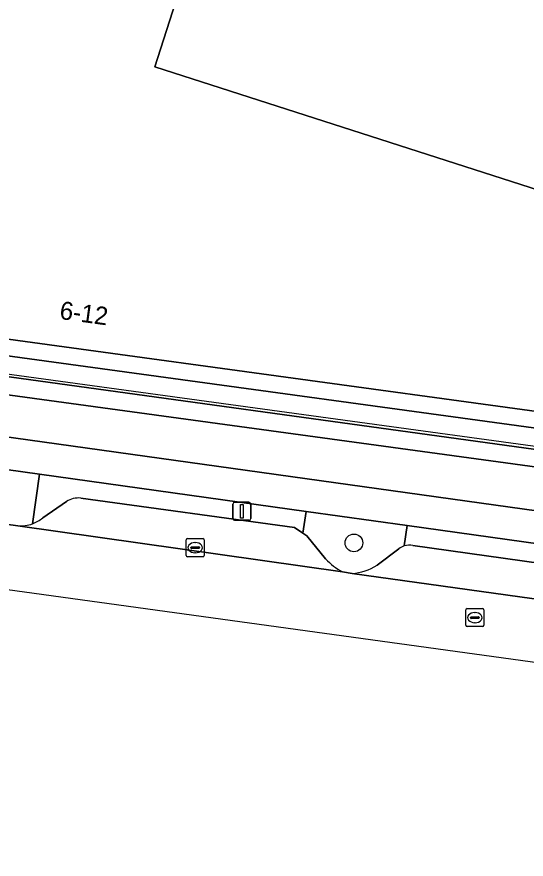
# Model space of a CAD drawing. Extents: x 160675 to 161153, y 383241 to 383714.
# Drawn here: x 160930.14 to 160958.41, y 383243.61 to 383290.36 of the extents above; entities that cross this region are included whole.
import ezdxf

# ---------------------------------------------------------------- set-up
doc = ezdxf.new("R2010")
doc.units = 0
for name, color, linetype in [('IMGEO_Berm_open', 7, 'Continuous'), ('IMGEO_Boom', 7, 'Continuous'), ('IMGEO_Erf', 7, 'Continuous'), ('IMGEO_Fietspad_gesloten', 7, 'Continuous'), ('IMGEO_Groenvoorziening', 7, 'Continuous'), ('IMGEO_Kolk', 7, 'Continuous'), ('IMGEO_Lichtmast', 7, 'Continuous'), ('IMGEO_Lijnafwatering', 7, 'Continuous'), ('IMGEO_Pand', 7, 'Continuous'), ('IMGEO_Pand_nummerreeks', 7, 'Continuous'), ('IMGEO_Parkeervlak_open', 7, 'Continuous'), ('IMGEO_Rijbaan_lokaal_gesloten', 7, 'Continuous'), ('IMGEO_Rioolput', 7, 'Continuous'), ('IMGEO_Voetpad_open', 7, 'Continuous')]:
    doc.layers.add(name, color=color, linetype=linetype)

msp = doc.modelspace()

# ---------------------------------------------------------------- linework, layer by layer
at = {"layer": 'IMGEO_Berm_open'}
for points in [[(160946.189, 383262.908), (160931.387, 383264.979), (160931.002, 383262.219)], [(160933.685, 383263.646), (160945.542, 383262.006), (160946.008, 383261.707), (160946.189, 383262.908)], [(160931.577, 383262.554), (160932.889, 383263.454)], [(160951.803, 383262.123), (160951.638, 383260.989)], [(160970.944, 383258.256), (160971.094, 383259.424), (160951.803, 383262.123)], [(160952.119, 383261.02), (160970.455, 383258.441)]]:
    msp.add_lwpolyline(points, dxfattribs=at)
for centre, radius, start, end in [((160933.559, 383262.422), 1.231, 84.1317, 122.9904), ((160930.363, 383263.977), 1.87, 289.9775, 310.4734), ((160951.941, 383260.039), 0.997, 79.704, 107.6711)]:
    msp.add_arc(centre, radius, start, end, dxfattribs=at)
at = {"layer": 'IMGEO_Boom'}
msp.add_circle((160948.846, 383261.16), 0.489, dxfattribs=at)
at = {"layer": 'IMGEO_Erf'}
msp.add_lwpolyline([(160943.614, 383302.795), (160942.777, 383303.077), (160942.578, 383302.465), (160941.73, 383302.736), (160940.32, 383298.343), (160941.191, 383298.065), (160940.991, 383297.445), (160940.143, 383297.716), (160938.625, 383292.988), (160939.448, 383292.73), (160937.804, 383287.581), (160963.866, 383279.201), (160968.854, 383294.685)], close=True, dxfattribs=at)
at = {"layer": 'IMGEO_Fietspad_gesloten'}
for points in [[(161055.654, 383249.406), (161021.974, 383254.146), (161015.584, 383255.032), (160917.876, 383268.672), (160905.957, 383270.323), (160821.26, 383282.051), (160802.2, 383284.6)], [(160916.557, 383267.054), (160927.544, 383265.517), (160931.387, 383264.979), (160946.189, 383262.908), (160951.803, 383262.123), (160971.094, 383259.424), (160976.57, 383258.658), (160989.408, 383256.862), (160994.582, 383256.138), (161009.264, 383254.084), (161014.233, 383253.389), (161021.034, 383252.455), (161029.904, 383251.214), (161035.545, 383250.425), (161050.235, 383248.369), (161054.045, 383247.836), (161056.61, 383247.477)]]:
    msp.add_lwpolyline(points, dxfattribs=at)
at = {"layer": 'IMGEO_Groenvoorziening'}
for points in [[(160931.387, 383264.979), (160927.544, 383265.517), (160927.098, 383262.525), (160930.19, 383262.116)], [(160931.002, 383262.219), (160931.387, 383264.979)], [(160951.803, 383262.123), (160946.189, 383262.908), (160946.008, 383261.707), (160946.238, 383261.56), (160947.276, 383260.282)], [(160951.638, 383260.989), (160951.803, 383262.123)], [(160950.129, 383259.921), (160951.342, 383260.833)], [(160948.208, 383259.553), (160948.745, 383259.454)]]:
    msp.add_lwpolyline(points, dxfattribs=at)
for centre, radius, start, end in [((160930.366, 383263.979), 1.871, 264.5955, 289.8629), ((160951.928, 383260.079), 0.955, 107.7036, 127.8773), ((160949.729, 383262.458), 3.279, 221.5745, 242.3612), ((160948.423, 383262.692), 3.254, 275.6766, 301.615)]:
    msp.add_arc(centre, radius, start, end, dxfattribs=at)
at = {"layer": 'IMGEO_Kolk'}
for p, q in [((160939.535, 383260.469), (160939.535, 383261.321)), ((160939.61, 383261.395), (160940.462, 383261.395)), ((160940.536, 383261.321), (160940.536, 383260.469)), ((160939.794, 383260.889), (160939.794, 383260.901)), ((160940.232, 383260.852), (160939.834, 383260.852)), ((160939.837, 383260.938), (160940.235, 383260.938)), ((160940.023, 383261.175), (160940.048, 383261.175)), ((160940.278, 383260.901), (160940.278, 383260.889)), ((160940.462, 383260.395), (160939.61, 383260.395)), ((160940.046, 383260.615), (160940.021, 383260.615))]:
    msp.add_line(p, q, dxfattribs=at)
for points in [[(160939.535, 383260.469), (160939.535, 383261.321)], [(160939.61, 383261.395), (160940.462, 383261.395)], [(160940.536, 383261.321), (160940.536, 383260.469)], [(160940.462, 383260.395), (160939.61, 383260.395)]]:
    msp.add_lwpolyline(points, dxfattribs=at)
for centre, radius, start, end in [((160939.612, 383261.319), 0.0765, 91.552, 178.448), ((160939.612, 383261.319), 0.0765, 91.552, 178.448), ((160940.46, 383261.319), 0.0765, 1.552, 88.448), ((160940.46, 383261.319), 0.0765, 1.552, 88.448), ((160939.834, 383260.898), 0.0403, 85.8775, 175.7526), ((160939.831, 383260.888), 0.0366, 178.938, 274.7102), ((160940.235, 383260.895), 0.043, 264.8664, 352.4533), ((160940.239, 383260.9), 0.0386, 1.7309, 96.639), ((160939.612, 383260.471), 0.0765, 181.552, 268.448), ((160939.612, 383260.471), 0.0765, 181.552, 268.448), ((160940.46, 383260.471), 0.0765, 271.552, 358.448), ((160940.46, 383260.471), 0.0765, 271.552, 358.448)]:
    msp.add_arc(centre, radius, start, end, dxfattribs=at)
for centre, major_axis, ratio, start_param, end_param in [((160940.022, 383260.895), (-0.387, 0.002), 0.722429, 4.712389, 7.853982), ((160940.047, 383260.895), (-0.39, 0.002), 0.717154, 1.570796, 4.712389)]:
    msp.add_ellipse(centre, major_axis=major_axis, ratio=ratio, start_param=start_param, end_param=end_param, dxfattribs=at)
at = {"layer": 'IMGEO_Lichtmast'}
for p, q in [((160942.126, 383262.515), (160942.126, 383263.315)), ((160942.126, 383263.315), (160942.126, 383262.515)), ((160942.226, 383263.415), (160943.016, 383263.415)), ((160943.016, 383263.415), (160942.226, 383263.415)), ((160943.116, 383263.315), (160943.116, 383262.515)), ((160943.116, 383262.515), (160943.116, 383263.315)), ((160943.016, 383262.415), (160942.226, 383262.415)), ((160942.226, 383262.415), (160943.016, 383262.415))]:
    msp.add_line(p, q, dxfattribs=at)
msp.add_lwpolyline([(160942.546, 383263.29), (160942.696, 383263.29), (160942.696, 383262.54), (160942.546, 383262.54), (160942.546, 383263.29)], dxfattribs=at)
for centre, start, end in [((160942.226, 383263.315), 90, 180), ((160942.226, 383263.315), 90, 180), ((160943.016, 383263.315), 0, 90), ((160943.016, 383263.315), 360, 90), ((160942.226, 383262.515), 180, 270), ((160942.226, 383262.515), 180, 270), ((160943.016, 383262.515), 270, 0), ((160943.016, 383262.515), 270, 0)]:
    msp.add_arc(centre, 0.1, start, end, dxfattribs=at)
at = {"layer": 'IMGEO_Lijnafwatering'}
for points in [[(160931.212, 383270.307), (160913.243, 383272.77)], [(160949.181, 383267.844), (160931.212, 383270.307)], [(160967.149, 383265.381), (160949.181, 383267.844)]]:
    msp.add_lwpolyline(points, dxfattribs=at)
at = {"layer": 'IMGEO_Pand'}
msp.add_lwpolyline([(160920.037, 383273.784), (160958.187, 383268.56), (160960.344, 383268.267), (160963.866, 383279.201), (160937.804, 383287.581), (160939.448, 383292.73), (160938.625, 383292.988), (160940.143, 383297.716), (160940.991, 383297.445), (160941.191, 383298.065), (160940.32, 383298.343), (160941.73, 383302.736), (160942.578, 383302.465), (160942.777, 383303.077), (160933.386, 383306.103), (160933.536, 383306.474), (160933.134, 383306.606), (160932.393, 383304.302), (160927.197, 383305.975)], dxfattribs=at)
at = {"layer": 'IMGEO_Parkeervlak_open'}
for points in [[(160945.542, 383262.006), (160933.685, 383263.646)], [(160932.889, 383263.454), (160931.577, 383262.554)], [(160930.19, 383262.116), (160948.208, 383259.553)], [(160947.276, 383260.282), (160946.238, 383261.56), (160946.008, 383261.707), (160945.542, 383262.006)], [(160951.342, 383260.833), (160950.129, 383259.921)], [(160970.455, 383258.441), (160952.119, 383261.02)], [(160948.745, 383259.454), (160973.076, 383256.077)]]:
    msp.add_lwpolyline(points, dxfattribs=at)
for centre, radius, start, end in [((160933.559, 383262.422), 1.231, 84.1317, 122.9904), ((160930.366, 383263.979), 1.871, 264.5955, 289.8629), ((160930.363, 383263.977), 1.87, 289.9775, 310.4734), ((160951.928, 383260.079), 0.955, 107.7036, 127.8773), ((160951.941, 383260.039), 0.997, 79.704, 107.6711), ((160949.729, 383262.458), 3.279, 221.5745, 242.3612), ((160948.423, 383262.692), 3.254, 275.6766, 301.615)]:
    msp.add_arc(centre, radius, start, end, dxfattribs=at)
at = {"layer": 'IMGEO_Rijbaan_lokaal_gesloten'}
msp.add_lwpolyline([(160991.33, 383253.522), (160973.717, 383255.972), (160973.076, 383256.077), (160948.745, 383259.454), (160948.208, 383259.553), (160930.19, 383262.116), (160927.098, 383262.525), (160926.821, 383262.562), (160926.374, 383259.023), (161038.265, 383243.607)], dxfattribs=at)
at = {"layer": 'IMGEO_Rioolput'}
for p, q in [((160955.133, 383257.511), (160955.985, 383257.511)), ((160955.058, 383256.585), (160955.058, 383257.437)), ((160955.317, 383257.005), (160955.317, 383257.017)), ((160955.36, 383257.054), (160955.758, 383257.054)), ((160955.546, 383257.291), (160955.571, 383257.291)), ((160955.801, 383257.017), (160955.801, 383257.005)), ((160956.059, 383257.437), (160956.059, 383256.585)), ((160955.755, 383256.968), (160955.357, 383256.968)), ((160955.569, 383256.731), (160955.544, 383256.731)), ((160955.985, 383256.511), (160955.133, 383256.511))]:
    msp.add_line(p, q, dxfattribs=at)
for points in [[(160955.133, 383257.511), (160955.985, 383257.511)], [(160955.058, 383256.585), (160955.058, 383257.437)], [(160956.059, 383257.437), (160956.059, 383256.585)], [(160955.985, 383256.511), (160955.133, 383256.511)]]:
    msp.add_lwpolyline(points, dxfattribs=at)
for centre, radius, start, end in [((160955.135, 383257.435), 0.0765, 91.552, 178.448), ((160955.135, 383257.435), 0.0765, 91.552, 178.448), ((160955.983, 383257.435), 0.0765, 1.552, 88.448), ((160955.983, 383257.435), 0.0765, 1.552, 88.448), ((160955.357, 383257.014), 0.0403, 85.8775, 175.7526), ((160955.354, 383257.004), 0.0366, 178.938, 274.7102), ((160955.758, 383257.011), 0.043, 264.8664, 352.4533), ((160955.762, 383257.016), 0.0386, 1.7309, 96.639), ((160955.135, 383256.587), 0.0765, 181.552, 268.448), ((160955.135, 383256.587), 0.0765, 181.552, 268.448), ((160955.983, 383256.587), 0.0765, 271.552, 358.448), ((160955.983, 383256.587), 0.0765, 271.552, 358.448)]:
    msp.add_arc(centre, radius, start, end, dxfattribs=at)
for centre, major_axis, ratio, start_param, end_param in [((160955.545, 383257.011), (-0.387, 0.002), 0.722429, 4.712389, 7.853982), ((160955.57, 383257.011), (-0.39, 0.002), 0.717154, 1.570796, 4.712389)]:
    msp.add_ellipse(centre, major_axis=major_axis, ratio=ratio, start_param=start_param, end_param=end_param, dxfattribs=at)
at = {"layer": 'IMGEO_Voetpad_open'}
for points in [[(160794.456, 383285.635), (160802.2, 383284.6), (160821.26, 383282.051), (160905.957, 383270.323), (160917.876, 383268.672), (161015.584, 383255.032)], [(160906.361, 383274.718), (160906.652, 383275.617), (160907.414, 383278.054), (160906.582, 383278.383), (160904.953, 383273.337), (160904.857, 383273.04), (160905.752, 383272.875), (160905.772, 383272.934), (160905.926, 383273.383), (160906.572, 383273.293), (160906.425, 383272.844), (160912.494, 383272.008), (160912.693, 383272.666), (160919.42, 383271.745), (160919.491, 383271.792), (160966.461, 383265.316), (160973.144, 383264.419), (160988.15, 383262.381)], [(160987.9, 383263.299), (160987.726, 383263.594), (160906.361, 383274.718)], [(160988.114, 383261.392), (160972.847, 383263.465), (160972.925, 383263.763), (160966.242, 383264.66), (160966.18, 383264.374), (160960.071, 383265.21), (160959.949, 383264.845), (160959.305, 383264.94), (160959.423, 383265.299), (160919.184, 383270.806), (160919.221, 383271.087), (160912.494, 383272.008), (160906.425, 383272.844), (160906.213, 383272.197), (160905.572, 383272.294), (160905.752, 383272.875)]]:
    msp.add_lwpolyline(points, dxfattribs=at)
for points in [[(160906.652, 383275.617), (160906.361, 383274.718), (160987.726, 383263.594), (160987.295, 383264.611), (160973.818, 383266.439), (160960.344, 383268.267), (160958.187, 383268.56), (160920.037, 383273.784)], [(160919.491, 383271.792), (160919.42, 383271.745), (160919.221, 383271.087), (160919.184, 383270.806), (160959.423, 383265.299), (160959.51, 383265.564), (160959.664, 383266.036), (160960.315, 383265.94), (160960.171, 383265.509), (160960.071, 383265.21), (160966.18, 383264.374), (160966.242, 383264.66), (160966.461, 383265.316)]]:
    msp.add_lwpolyline(points, close=True, dxfattribs=at)

# ---------------------------------------------------------------- texts
at = {"layer": 'IMGEO_Pand_nummerreeks'}
msp.add_text('6-12', height=1, rotation=352.202, dxfattribs=at).set_placement((160932.469, 383273.595))

doc.saveas('drawing.dxf')
